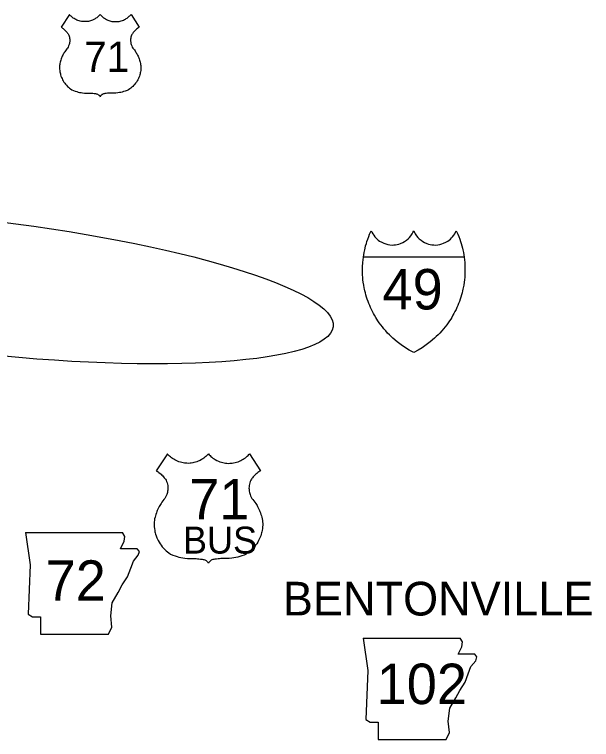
# Model space of a CAD drawing. Extents: x 6028647 to 6035072, y 5366486 to 5368495.
# Drawn here: x 6029055.1 to 6029190.7, y 5368118.9 to 5368289.4 of the extents above; entities that cross this region are included whole.
import ezdxf

# ---------------------------------------------------------------- set-up
doc = ezdxf.new("R2010")
doc.units = 0
for name, color, linetype in [('21', 7, 'Continuous'), ('22', 7, 'Continuous'), ('23', 7, 'Continuous'), ('25', 7, 'Continuous'), ('Level 1', 7, 'Continuous')]:
    doc.layers.add(name, color=color, linetype=linetype)

msp = doc.modelspace()

# ---------------------------------------------------------------- linework, layer by layer
at = {"layer": '21'}
for p, q in [((6029057.69, 5368167.6), (6029058.83, 5368159.99)), ((6029081.03, 5368166.71), (6029080.51, 5368167.59)), ((6029080.91, 5368165.57), (6029081.03, 5368166.71)), ((6029080.02, 5368163.79), (6029080.91, 5368165.57)), ((6029083.95, 5368163.79), (6029080.02, 5368163.79)), ((6029084.46, 5368163.16), (6029083.95, 5368163.79)), ((6029084.2, 5368162.27), (6029084.46, 5368163.16)), ((6029083.06, 5368160.87), (6029084.2, 5368162.27)), ((6029058.83, 5368159.99), (6029058.32, 5368148.44)), ((6029082.43, 5368159.22), (6029083.06, 5368160.87)), ((6029081.67, 5368157.19), (6029082.43, 5368159.22)), ((6029080.4, 5368155.29), (6029081.67, 5368157.19)), ((6029079.51, 5368153.51), (6029080.4, 5368155.29)), ((6029078.11, 5368151.1), (6029079.51, 5368153.51)), ((6029077.73, 5368148.06), (6029078.11, 5368151.1)), ((6029058.32, 5368148.44), (6029059.34, 5368147.8)), ((6029077.99, 5368145.39), (6029077.73, 5368148.06)), ((6029059.34, 5368147.8), (6029061.24, 5368147.8)), ((6029061.24, 5368147.8), (6029061.24, 5368143.74)), ((6029077.23, 5368143.74), (6029077.99, 5368145.39)), ((6029061.24, 5368143.74), (6029077.23, 5368143.74)), ((6029137.02, 5368142.8), (6029138.16, 5368135.19)), ((6029160.36, 5368141.92), (6029159.84, 5368142.79)), ((6029160.24, 5368140.77), (6029160.36, 5368141.92)), ((6029159.35, 5368139), (6029160.24, 5368140.77)), ((6029163.28, 5368139), (6029159.35, 5368139)), ((6029163.79, 5368138.36), (6029163.28, 5368139)), ((6029163.53, 5368137.47), (6029163.79, 5368138.36)), ((6029161.76, 5368134.43), (6029162.39, 5368136.08)), ((6029162.39, 5368136.08), (6029163.53, 5368137.47)), ((6029138.16, 5368135.19), (6029137.65, 5368123.64)), ((6029161, 5368132.4), (6029161.76, 5368134.43)), ((6029159.73, 5368130.5), (6029161, 5368132.4)), ((6029158.84, 5368128.72), (6029159.73, 5368130.5)), ((6029157.44, 5368126.31), (6029158.84, 5368128.72)), ((6029157.06, 5368123.26), (6029157.44, 5368126.31)), ((6029137.65, 5368123.64), (6029138.67, 5368123.01)), ((6029138.67, 5368123.01), (6029140.57, 5368123.01)), ((6029140.57, 5368123.01), (6029140.57, 5368118.95)), ((6029157.32, 5368120.6), (6029157.06, 5368123.26)), ((6029156.56, 5368118.95), (6029157.32, 5368120.6)), ((6029140.57, 5368118.95), (6029156.56, 5368118.95))]:
    msp.add_line(p, q, dxfattribs=at)
for points in [[(6029057.69, 5368167.6), (6029080.51, 5368167.59)], [(6029137.02, 5368142.8), (6029159.84, 5368142.79)]]:
    msp.add_lwpolyline(points, dxfattribs=at)
at = {"layer": '22'}
for points in [[(6029075.26, 5368289.42), (6029075.11, 5368289.25), (6029074.97, 5368289.11), (6029074.81, 5368288.96), (6029074.64, 5368288.81), (6029074.47, 5368288.68), (6029074.27, 5368288.54), (6029074.05, 5368288.4), (6029073.8, 5368288.26), (6029073.48, 5368288.12), (6029073.24, 5368288.02), (6029072.97, 5368287.94), (6029072.72, 5368287.87), (6029072.49, 5368287.82), (6029072.25, 5368287.78), (6029072.02, 5368287.76), (6029071.72, 5368287.75), (6029071.47, 5368287.75), (6029071.25, 5368287.76), (6029071.05, 5368287.79), (6029070.84, 5368287.82), (6029070.57, 5368287.87), (6029070.33, 5368287.93), (6029070.03, 5368288.03), (6029069.78, 5368288.13), (6029069.56, 5368288.23), (6029069.35, 5368288.34), (6029069.15, 5368288.46), (6029068.94, 5368288.6), (6029068.74, 5368288.74), (6029068.57, 5368288.88), (6029068.43, 5368289.01), (6029068.28, 5368289.15), (6029068.14, 5368289.3), (6029068.02, 5368289.44), (6029066.07, 5368286.42), (6029066.21, 5368286.34), (6029066.38, 5368286.23), (6029066.54, 5368286.12), (6029066.75, 5368285.96), (6029066.91, 5368285.81), (6029067.06, 5368285.68), (6029067.21, 5368285.52), (6029067.37, 5368285.35), (6029067.48, 5368285.22), (6029067.59, 5368285.08), (6029067.7, 5368284.92), (6029067.8, 5368284.76), (6029067.9, 5368284.57), (6029067.98, 5368284.33), (6029068.04, 5368284.1), (6029068.08, 5368283.85), (6029068.1, 5368283.62), (6029068.11, 5368283.4), (6029068.11, 5368283.19), (6029068.09, 5368283.02), (6029068.06, 5368282.82), (6029068.03, 5368282.62), (6029067.97, 5368282.41), (6029067.91, 5368282.23), (6029067.83, 5368282.03), (6029067.71, 5368281.76), (6029067.58, 5368281.55), (6029067.42, 5368281.36), (6029067.23, 5368281.12), (6029067.08, 5368280.9), (6029066.93, 5368280.69), (6029066.8, 5368280.48), (6029066.69, 5368280.29), (6029066.59, 5368280.11), (6029066.48, 5368279.9), (6029066.36, 5368279.66), (6029066.26, 5368279.42), (6029066.18, 5368279.24), (6029066.1, 5368279.01), (6029066, 5368278.73), (6029065.93, 5368278.5), (6029065.86, 5368278.24), (6029065.79, 5368277.95), (6029065.75, 5368277.68), (6029065.72, 5368277.41), (6029065.7, 5368277.11), (6029065.7, 5368276.83), (6029065.71, 5368276.55), (6029065.74, 5368276.23), (6029065.79, 5368275.92), (6029065.84, 5368275.69), (6029065.9, 5368275.49), (6029065.96, 5368275.26), (6029066.05, 5368274.97), (6029066.18, 5368274.63), (6029066.29, 5368274.37), (6029066.42, 5368274.11), (6029066.56, 5368273.85), (6029066.75, 5368273.55), (6029066.93, 5368273.28), (6029067.12, 5368273.05), (6029067.33, 5368272.8), (6029067.6, 5368272.52), (6029067.82, 5368272.31), (6029068.06, 5368272.12)], [(6029075.26, 5368289.42), (6029075.41, 5368289.25), (6029075.55, 5368289.11), (6029075.71, 5368288.96), (6029075.88, 5368288.81), (6029076.05, 5368288.68), (6029076.26, 5368288.54), (6029076.47, 5368288.4), (6029076.72, 5368288.26), (6029077.04, 5368288.12), (6029077.28, 5368288.02), (6029077.55, 5368287.94), (6029077.8, 5368287.87), (6029078.03, 5368287.82), (6029078.28, 5368287.78), (6029078.5, 5368287.76), (6029078.81, 5368287.75), (6029079.05, 5368287.75), (6029079.27, 5368287.76), (6029079.48, 5368287.79), (6029079.69, 5368287.82), (6029079.95, 5368287.87), (6029080.19, 5368287.93), (6029080.49, 5368288.03), (6029080.74, 5368288.13), (6029080.97, 5368288.23), (6029081.17, 5368288.34), (6029081.37, 5368288.46), (6029081.58, 5368288.6), (6029081.78, 5368288.74), (6029081.95, 5368288.88), (6029082.09, 5368289.01), (6029082.24, 5368289.15), (6029082.38, 5368289.3), (6029082.5, 5368289.44), (6029084.45, 5368286.42), (6029084.31, 5368286.34), (6029084.14, 5368286.23), (6029083.99, 5368286.12), (6029083.78, 5368285.96), (6029083.61, 5368285.81), (6029083.46, 5368285.68), (6029083.31, 5368285.52), (6029083.16, 5368285.35), (6029083.04, 5368285.22), (6029082.94, 5368285.08), (6029082.82, 5368284.92), (6029082.72, 5368284.76), (6029082.62, 5368284.57), (6029082.54, 5368284.33), (6029082.48, 5368284.1), (6029082.44, 5368283.85), (6029082.42, 5368283.62), (6029082.41, 5368283.4), (6029082.42, 5368283.19), (6029082.43, 5368283.02), (6029082.46, 5368282.82), (6029082.49, 5368282.62), (6029082.55, 5368282.41), (6029082.61, 5368282.23), (6029082.69, 5368282.03), (6029082.81, 5368281.76), (6029082.94, 5368281.55), (6029083.1, 5368281.36), (6029083.29, 5368281.12), (6029083.45, 5368280.9), (6029083.59, 5368280.69), (6029083.72, 5368280.48), (6029083.83, 5368280.29), (6029083.93, 5368280.11), (6029084.04, 5368279.9), (6029084.16, 5368279.66), (6029084.27, 5368279.42), (6029084.34, 5368279.24), (6029084.42, 5368279.01), (6029084.52, 5368278.73), (6029084.59, 5368278.5), (6029084.67, 5368278.24), (6029084.73, 5368277.95), (6029084.77, 5368277.68), (6029084.81, 5368277.41), (6029084.82, 5368277.11), (6029084.82, 5368276.83), (6029084.81, 5368276.55), (6029084.78, 5368276.23), (6029084.73, 5368275.92), (6029084.68, 5368275.69), (6029084.62, 5368275.49), (6029084.56, 5368275.26), (6029084.47, 5368274.97), (6029084.34, 5368274.63), (6029084.23, 5368274.37), (6029084.1, 5368274.11), (6029083.96, 5368273.85), (6029083.78, 5368273.55), (6029083.59, 5368273.28), (6029083.4, 5368273.05), (6029083.2, 5368272.8), (6029082.93, 5368272.52), (6029082.7, 5368272.31), (6029082.46, 5368272.12)], [(6029068.06, 5368272.12), (6029068.3, 5368271.93), (6029068.6, 5368271.74), (6029068.97, 5368271.58), (6029069.4, 5368271.41), (6029069.75, 5368271.3), (6029070.06, 5368271.21), (6029070.42, 5368271.12), (6029070.76, 5368271.06), (6029071.12, 5368271.01), (6029071.58, 5368270.97), (6029071.92, 5368270.96), (6029072.22, 5368270.96), (6029072.51, 5368270.96), (6029072.8, 5368270.95), (6029073.08, 5368270.94), (6029073.32, 5368270.92), (6029073.55, 5368270.9), (6029073.86, 5368270.87), (6029074.15, 5368270.83), (6029074.33, 5368270.81), (6029074.48, 5368270.78), (6029074.65, 5368270.71), (6029074.75, 5368270.65), (6029074.84, 5368270.59), (6029074.96, 5368270.49), (6029075.08, 5368270.38), (6029075.18, 5368270.25), (6029075.26, 5368270.11)], [(6029082.46, 5368272.12), (6029082.22, 5368271.93), (6029081.92, 5368271.74), (6029081.56, 5368271.58), (6029081.13, 5368271.41), (6029080.77, 5368271.3), (6029080.46, 5368271.21), (6029080.1, 5368271.12), (6029079.76, 5368271.06), (6029079.4, 5368271.01), (6029078.95, 5368270.97), (6029078.6, 5368270.96), (6029078.3, 5368270.96), (6029078.01, 5368270.96), (6029077.72, 5368270.95), (6029077.44, 5368270.94), (6029077.2, 5368270.92), (6029076.97, 5368270.9), (6029076.67, 5368270.87), (6029076.37, 5368270.83), (6029076.19, 5368270.81), (6029076.05, 5368270.78), (6029075.87, 5368270.71), (6029075.77, 5368270.65), (6029075.68, 5368270.59), (6029075.56, 5368270.49), (6029075.44, 5368270.38), (6029075.35, 5368270.25), (6029075.26, 5368270.11)], [(6029100.69, 5368186.12), (6029100.49, 5368185.9), (6029100.3, 5368185.71), (6029100.09, 5368185.51), (6029099.86, 5368185.31), (6029099.63, 5368185.14), (6029099.36, 5368184.95), (6029099.07, 5368184.76), (6029098.74, 5368184.58), (6029098.32, 5368184.39), (6029098, 5368184.26), (6029097.64, 5368184.14), (6029097.3, 5368184.06), (6029096.99, 5368183.99), (6029096.67, 5368183.94), (6029096.37, 5368183.91), (6029095.96, 5368183.89), (6029095.63, 5368183.9), (6029095.34, 5368183.92), (6029095.07, 5368183.95), (6029094.79, 5368183.99), (6029094.44, 5368184.06), (6029094.12, 5368184.14), (6029093.72, 5368184.27), (6029093.39, 5368184.4), (6029093.08, 5368184.54), (6029092.81, 5368184.69), (6029092.55, 5368184.84), (6029092.26, 5368185.03), (6029092, 5368185.22), (6029091.77, 5368185.41), (6029091.58, 5368185.58), (6029091.39, 5368185.77), (6029091.19, 5368185.97), (6029091.04, 5368186.14), (6029088.44, 5368182.13), (6029088.63, 5368182.02), (6029088.85, 5368181.87), (6029089.06, 5368181.73), (6029089.34, 5368181.51), (6029089.56, 5368181.32), (6029089.76, 5368181.13), (6029089.96, 5368180.93), (6029090.16, 5368180.7), (6029090.31, 5368180.52), (6029090.46, 5368180.33), (6029090.61, 5368180.13), (6029090.75, 5368179.91), (6029090.88, 5368179.65), (6029090.98, 5368179.34), (6029091.06, 5368179.03), (6029091.12, 5368178.7), (6029091.15, 5368178.39), (6029091.16, 5368178.09), (6029091.15, 5368177.82), (6029091.13, 5368177.59), (6029091.1, 5368177.32), (6029091.04, 5368177.06), (6029090.97, 5368176.78), (6029090.89, 5368176.54), (6029090.79, 5368176.27), (6029090.62, 5368175.91), (6029090.45, 5368175.63), (6029090.24, 5368175.38), (6029089.98, 5368175.06), (6029089.78, 5368174.77), (6029089.58, 5368174.48), (6029089.41, 5368174.2), (6029089.26, 5368173.95), (6029089.13, 5368173.72), (6029088.98, 5368173.44), (6029088.82, 5368173.11), (6029088.68, 5368172.79), (6029088.59, 5368172.55), (6029088.47, 5368172.24), (6029088.35, 5368171.87), (6029088.25, 5368171.56), (6029088.15, 5368171.22), (6029088.06, 5368170.83), (6029088.01, 5368170.48), (6029087.96, 5368170.11), (6029087.94, 5368169.71), (6029087.94, 5368169.34), (6029087.96, 5368168.97), (6029088, 5368168.54), (6029088.07, 5368168.13), (6029088.13, 5368167.82), (6029088.2, 5368167.55), (6029088.29, 5368167.24), (6029088.41, 5368166.86), (6029088.58, 5368166.4), (6029088.73, 5368166.06), (6029088.9, 5368165.71), (6029089.09, 5368165.37), (6029089.34, 5368164.97), (6029089.59, 5368164.61), (6029089.83, 5368164.29), (6029090.11, 5368163.97), (6029090.47, 5368163.6), (6029090.77, 5368163.32), (6029091.09, 5368163.05)], [(6029100.69, 5368186.12), (6029100.89, 5368185.9), (6029101.08, 5368185.71), (6029101.29, 5368185.51), (6029101.52, 5368185.31), (6029101.75, 5368185.14), (6029102.02, 5368184.95), (6029102.31, 5368184.76), (6029102.64, 5368184.58), (6029103.06, 5368184.39), (6029103.38, 5368184.26), (6029103.74, 5368184.14), (6029104.08, 5368184.06), (6029104.39, 5368183.99), (6029104.71, 5368183.94), (6029105.01, 5368183.91), (6029105.42, 5368183.89), (6029105.75, 5368183.9), (6029106.04, 5368183.92), (6029106.31, 5368183.95), (6029106.59, 5368183.99), (6029106.94, 5368184.06), (6029107.26, 5368184.14), (6029107.66, 5368184.27), (6029107.99, 5368184.4), (6029108.3, 5368184.54), (6029108.57, 5368184.69), (6029108.83, 5368184.84), (6029109.12, 5368185.03), (6029109.38, 5368185.22), (6029109.61, 5368185.41), (6029109.8, 5368185.58), (6029110, 5368185.77), (6029110.19, 5368185.97), (6029110.34, 5368186.14), (6029112.94, 5368182.13), (6029112.75, 5368182.02), (6029112.53, 5368181.87), (6029112.32, 5368181.73), (6029112.04, 5368181.51), (6029111.82, 5368181.32), (6029111.62, 5368181.13), (6029111.42, 5368180.93), (6029111.22, 5368180.7), (6029111.07, 5368180.52), (6029110.92, 5368180.33), (6029110.78, 5368180.13), (6029110.63, 5368179.91), (6029110.5, 5368179.65), (6029110.4, 5368179.34), (6029110.32, 5368179.03), (6029110.26, 5368178.7), (6029110.23, 5368178.39), (6029110.22, 5368178.09), (6029110.23, 5368177.82), (6029110.25, 5368177.59), (6029110.29, 5368177.32), (6029110.34, 5368177.06), (6029110.41, 5368176.78), (6029110.49, 5368176.54), (6029110.59, 5368176.27), (6029110.76, 5368175.91), (6029110.93, 5368175.63), (6029111.14, 5368175.38), (6029111.4, 5368175.06), (6029111.6, 5368174.77), (6029111.8, 5368174.48), (6029111.97, 5368174.2), (6029112.12, 5368173.95), (6029112.25, 5368173.72), (6029112.4, 5368173.44), (6029112.56, 5368173.11), (6029112.7, 5368172.79), (6029112.79, 5368172.55), (6029112.91, 5368172.24), (6029113.03, 5368171.87), (6029113.14, 5368171.56), (6029113.23, 5368171.22), (6029113.32, 5368170.83), (6029113.37, 5368170.48), (6029113.42, 5368170.11), (6029113.44, 5368169.71), (6029113.44, 5368169.34), (6029113.42, 5368168.97), (6029113.38, 5368168.54), (6029113.31, 5368168.13), (6029113.25, 5368167.82), (6029113.18, 5368167.55), (6029113.09, 5368167.24), (6029112.97, 5368166.86), (6029112.8, 5368166.4), (6029112.65, 5368166.06), (6029112.48, 5368165.71), (6029112.29, 5368165.37), (6029112.04, 5368164.97), (6029111.79, 5368164.61), (6029111.55, 5368164.29), (6029111.27, 5368163.97), (6029110.91, 5368163.6), (6029110.61, 5368163.32), (6029110.29, 5368163.05)], [(6029091.09, 5368163.05), (6029091.41, 5368162.81), (6029091.8, 5368162.55), (6029092.3, 5368162.33), (6029092.87, 5368162.11), (6029093.34, 5368161.96), (6029093.76, 5368161.84), (6029094.24, 5368161.73), (6029094.69, 5368161.65), (6029095.17, 5368161.58), (6029095.78, 5368161.53), (6029096.24, 5368161.51), (6029096.64, 5368161.52), (6029097.02, 5368161.51), (6029097.41, 5368161.5), (6029097.78, 5368161.48), (6029098.1, 5368161.46), (6029098.41, 5368161.43), (6029098.82, 5368161.39), (6029099.21, 5368161.34), (6029099.45, 5368161.31), (6029099.64, 5368161.27), (6029099.88, 5368161.17), (6029100.01, 5368161.1), (6029100.13, 5368161.02), (6029100.29, 5368160.89), (6029100.45, 5368160.73), (6029100.58, 5368160.57), (6029100.69, 5368160.38)], [(6029110.29, 5368163.05), (6029109.97, 5368162.81), (6029109.58, 5368162.55), (6029109.08, 5368162.33), (6029108.51, 5368162.11), (6029108.04, 5368161.96), (6029107.62, 5368161.84), (6029107.14, 5368161.73), (6029106.69, 5368161.65), (6029106.21, 5368161.58), (6029105.6, 5368161.53), (6029105.14, 5368161.51), (6029104.74, 5368161.52), (6029104.36, 5368161.51), (6029103.97, 5368161.5), (6029103.6, 5368161.48), (6029103.28, 5368161.46), (6029102.97, 5368161.43), (6029102.56, 5368161.39), (6029102.17, 5368161.34), (6029101.93, 5368161.31), (6029101.74, 5368161.27), (6029101.5, 5368161.17), (6029101.37, 5368161.1), (6029101.25, 5368161.02), (6029101.09, 5368160.89), (6029100.93, 5368160.73), (6029100.8, 5368160.57), (6029100.69, 5368160.38)]]:
    msp.add_lwpolyline(points, dxfattribs=at)
at = {"layer": '23'}
for points in [[(6029137.11, 5368232.38), (6029137.19, 5368232.95), (6029137.28, 5368233.45), (6029137.41, 5368234.09), (6029137.51, 5368234.51), (6029137.64, 5368235.01), (6029137.8, 5368235.6), (6029137.95, 5368236.09), (6029138.12, 5368236.59), (6029138.35, 5368237.21), (6029138.58, 5368237.79), (6029138.77, 5368238.25), (6029138.94, 5368238.6), (6029139.11, 5368238.22), (6029139.31, 5368237.85), (6029139.53, 5368237.52), (6029139.82, 5368237.14), (6029140.05, 5368236.89), (6029140.33, 5368236.62), (6029140.61, 5368236.38), (6029140.92, 5368236.16), (6029141.41, 5368235.86), (6029141.92, 5368235.63), (6029142.37, 5368235.47), (6029142.82, 5368235.35), (6029143.3, 5368235.27), (6029143.87, 5368235.23), (6029144.24, 5368235.24), (6029144.66, 5368235.28), (6029145.04, 5368235.35), (6029145.44, 5368235.45), (6029145.85, 5368235.58), (6029146.39, 5368235.82), (6029146.77, 5368236.03), (6029147.21, 5368236.33), (6029147.63, 5368236.69), (6029147.94, 5368237), (6029148.29, 5368237.42), (6029148.58, 5368237.85), (6029148.75, 5368238.16), (6029148.93, 5368238.56)], [(6029137.11, 5368232.38), (6029137.19, 5368232.95), (6029137.28, 5368233.45), (6029137.41, 5368234.09), (6029137.51, 5368234.51), (6029137.64, 5368235.01), (6029137.8, 5368235.6), (6029137.95, 5368236.09), (6029138.12, 5368236.59), (6029138.35, 5368237.21), (6029138.58, 5368237.79), (6029138.77, 5368238.25), (6029138.94, 5368238.6), (6029139.11, 5368238.22), (6029139.31, 5368237.85), (6029139.53, 5368237.52), (6029139.82, 5368237.14), (6029140.05, 5368236.89), (6029140.33, 5368236.62), (6029140.61, 5368236.38), (6029140.92, 5368236.16), (6029141.41, 5368235.86), (6029141.92, 5368235.63), (6029142.37, 5368235.47), (6029142.82, 5368235.35), (6029143.3, 5368235.27), (6029143.87, 5368235.23), (6029144.24, 5368235.24), (6029144.66, 5368235.28), (6029145.04, 5368235.35), (6029145.44, 5368235.45), (6029145.85, 5368235.58), (6029146.39, 5368235.82), (6029146.77, 5368236.03), (6029147.21, 5368236.33), (6029147.63, 5368236.69), (6029147.94, 5368237), (6029148.29, 5368237.42), (6029148.58, 5368237.85), (6029148.75, 5368238.16), (6029148.93, 5368238.56)], [(6029148.93, 5368238.56), (6029149.12, 5368238.16), (6029149.29, 5368237.85), (6029149.58, 5368237.42), (6029149.93, 5368237), (6029150.24, 5368236.69), (6029150.66, 5368236.33), (6029151.1, 5368236.03), (6029151.47, 5368235.82), (6029152.02, 5368235.58), (6029152.43, 5368235.45), (6029152.83, 5368235.35), (6029153.21, 5368235.28), (6029153.63, 5368235.24), (6029154, 5368235.23), (6029154.56, 5368235.27), (6029155.05, 5368235.35), (6029155.5, 5368235.47), (6029155.95, 5368235.63), (6029156.46, 5368235.86), (6029156.95, 5368236.16), (6029157.26, 5368236.38), (6029157.54, 5368236.62), (6029157.82, 5368236.89), (6029158.05, 5368237.14), (6029158.34, 5368237.52), (6029158.56, 5368237.85), (6029158.76, 5368238.22), (6029158.93, 5368238.6), (6029159.09, 5368238.25), (6029159.29, 5368237.79), (6029159.52, 5368237.21), (6029159.74, 5368236.59), (6029159.91, 5368236.09), (6029160.06, 5368235.6), (6029160.23, 5368235.01), (6029160.36, 5368234.51), (6029160.45, 5368234.09), (6029160.59, 5368233.45), (6029160.68, 5368232.95), (6029160.76, 5368232.38)], [(6029148.93, 5368238.56), (6029149.12, 5368238.16), (6029149.29, 5368237.85), (6029149.58, 5368237.42), (6029149.93, 5368237), (6029150.24, 5368236.69), (6029150.66, 5368236.33), (6029151.1, 5368236.03), (6029151.47, 5368235.82), (6029152.02, 5368235.58), (6029152.43, 5368235.45), (6029152.83, 5368235.35), (6029153.21, 5368235.28), (6029153.63, 5368235.24), (6029154, 5368235.23), (6029154.56, 5368235.27), (6029155.05, 5368235.35), (6029155.5, 5368235.47), (6029155.95, 5368235.63), (6029156.46, 5368235.86), (6029156.95, 5368236.16), (6029157.26, 5368236.38), (6029157.54, 5368236.62), (6029157.82, 5368236.89), (6029158.05, 5368237.14), (6029158.34, 5368237.52), (6029158.56, 5368237.85), (6029158.76, 5368238.22), (6029158.93, 5368238.6), (6029159.09, 5368238.25), (6029159.29, 5368237.79), (6029159.52, 5368237.21), (6029159.74, 5368236.59), (6029159.91, 5368236.09), (6029160.06, 5368235.6), (6029160.23, 5368235.01), (6029160.36, 5368234.51), (6029160.45, 5368234.09), (6029160.59, 5368233.45), (6029160.68, 5368232.95), (6029160.76, 5368232.38)], [(6029148.93, 5368209.97), (6029147.9, 5368210.53), (6029146.99, 5368211.08), (6029145.98, 5368211.75), (6029145.05, 5368212.46), (6029144.02, 5368213.34), (6029143.64, 5368213.69), (6029143.21, 5368214.12), (6029142.8, 5368214.53), (6029142.36, 5368215.01), (6029141.93, 5368215.52), (6029141.57, 5368215.96), (6029141.18, 5368216.47), (6029140.82, 5368216.96), (6029140.51, 5368217.42), (6029140.24, 5368217.83), (6029140.02, 5368218.19), (6029139.72, 5368218.7), (6029139.49, 5368219.11), (6029139.24, 5368219.6), (6029138.99, 5368220.1), (6029138.78, 5368220.56), (6029138.59, 5368221.01), (6029138.38, 5368221.51), (6029138.21, 5368221.97), (6029138.03, 5368222.46), (6029137.87, 5368222.96), (6029137.71, 5368223.48), (6029137.58, 5368223.98), (6029137.46, 5368224.45), (6029137.36, 5368224.86), (6029137.3, 5368225.17), (6029137.19, 5368225.78), (6029137.08, 5368226.47), (6029137.01, 5368227.05), (6029136.95, 5368227.66), (6029136.92, 5368228.16), (6029136.9, 5368228.78), (6029136.89, 5368229.37), (6029136.9, 5368230.02), (6029136.92, 5368230.45), (6029136.95, 5368230.84), (6029136.96, 5368231.09), (6029137.02, 5368231.73), (6029137.11, 5368232.38)], [(6029160.76, 5368232.38), (6029137.11, 5368232.38)], [(6029160.76, 5368232.38), (6029137.11, 5368232.38)], [(6029160.76, 5368232.38), (6029160.84, 5368231.73), (6029160.91, 5368231.09), (6029160.92, 5368230.84), (6029160.95, 5368230.45), (6029160.97, 5368230.02), (6029160.98, 5368229.37), (6029160.97, 5368228.78), (6029160.95, 5368228.16), (6029160.92, 5368227.66), (6029160.86, 5368227.05), (6029160.79, 5368226.47), (6029160.68, 5368225.78), (6029160.57, 5368225.17), (6029160.5, 5368224.86), (6029160.41, 5368224.45), (6029160.29, 5368223.98), (6029160.16, 5368223.48), (6029160, 5368222.96), (6029159.83, 5368222.46), (6029159.66, 5368221.97), (6029159.49, 5368221.51), (6029159.28, 5368221.01), (6029159.09, 5368220.56), (6029158.87, 5368220.1), (6029158.63, 5368219.6), (6029158.37, 5368219.11), (6029158.14, 5368218.7), (6029157.85, 5368218.19), (6029157.63, 5368217.83), (6029157.35, 5368217.42), (6029157.05, 5368216.96), (6029156.69, 5368216.47), (6029156.3, 5368215.96), (6029155.94, 5368215.52), (6029155.51, 5368215.01), (6029155.06, 5368214.53), (6029154.66, 5368214.12), (6029154.23, 5368213.69), (6029153.85, 5368213.34), (6029152.82, 5368212.46), (6029151.89, 5368211.75), (6029150.88, 5368211.08), (6029149.97, 5368210.53), (6029148.93, 5368209.97)], [(6029160.76, 5368232.38), (6029160.84, 5368231.73), (6029160.91, 5368231.09), (6029160.92, 5368230.84), (6029160.95, 5368230.45), (6029160.97, 5368230.02), (6029160.98, 5368229.37), (6029160.97, 5368228.78), (6029160.95, 5368228.16), (6029160.92, 5368227.66), (6029160.86, 5368227.05), (6029160.79, 5368226.47), (6029160.68, 5368225.78), (6029160.57, 5368225.17), (6029160.5, 5368224.86), (6029160.41, 5368224.45), (6029160.29, 5368223.98), (6029160.16, 5368223.48), (6029160, 5368222.96), (6029159.83, 5368222.46), (6029159.66, 5368221.97), (6029159.49, 5368221.51), (6029159.28, 5368221.01), (6029159.09, 5368220.56), (6029158.87, 5368220.1), (6029158.63, 5368219.6), (6029158.37, 5368219.11), (6029158.14, 5368218.7), (6029157.85, 5368218.19), (6029157.63, 5368217.83), (6029157.35, 5368217.42), (6029157.05, 5368216.96), (6029156.69, 5368216.47), (6029156.3, 5368215.96), (6029155.94, 5368215.52), (6029155.51, 5368215.01), (6029155.06, 5368214.53), (6029154.66, 5368214.12), (6029154.23, 5368213.69), (6029153.85, 5368213.34), (6029152.82, 5368212.46), (6029151.89, 5368211.75), (6029150.88, 5368211.08), (6029149.97, 5368210.53), (6029148.93, 5368209.97)]]:
    msp.add_lwpolyline(points, dxfattribs=at)
at = {"layer": 'Level 1'}
msp.add_ellipse((6029044.97, 5368225.67), major_axis=(85.04, -9.66), ratio=0.183736, dxfattribs=at)

# ---------------------------------------------------------------- texts
at = {"layer": '21'}
for s, p in [('72', (6029062.45, 5368151.57)), ('102', (6029140.23, 5368127.28))]:
    msp.add_text(s, height=9.504, dxfattribs=at).set_placement(p)
at = {"layer": '22'}
for s, height, p in [('71', 7.128, (6029071.48, 5368275.94)), ('49', 9.504, (6029141.61, 5368220.08)), ('71', 9.504, (6029096.19, 5368170.73)), ('BUS', 6.336, (6029094.7, 5368162.67))]:
    msp.add_text(s, height=height, dxfattribs=at).set_placement(p)
at = {"layer": '25'}
msp.add_text('BENTONVILLE', height=7.92, dxfattribs=at).set_placement((6029118.18, 5368148.11))

doc.saveas('drawing.dxf')
